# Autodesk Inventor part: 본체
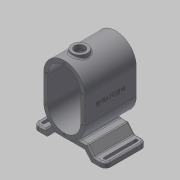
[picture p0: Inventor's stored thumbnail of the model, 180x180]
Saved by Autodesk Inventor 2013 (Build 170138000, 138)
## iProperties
Created: 2016-12
Part Number: 본체
Material: 알루미늄 6061
Document SubType Name: Modeling
Designer: mduedu
Density: 2.71 g/cm^3
Author: mduedu
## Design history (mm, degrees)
sketch "스케치1"
  geometry: L1 (40, -25)-(40, 25); L2 (-40, 25)-(-40, -25); L3 (-40, -25)-(40, 25); L4 (40, -25)-(-40, 25); L5 (0, 25)-(0, -25); A1 r 40 centre (0, 25) between (40, 25) and (-40, 25); A2 r 40 centre (0, -25) between (-40, -25) and (40, -25); 1 further point
  constraints: 10 end point, 4 point on circle, 3 tangent, 2 centre point, 2 midpoint, 2 parallel, 1 vertical
  dimensions: "d0" = 130 dimension on A2 A1; "d2" = 80 distance between parallel lines of L1 L2
extrude "돌출1" new body sketch "스케치1" stored distance "d3" = 100; taper "d4" = 0 deg
feature "쉘1" dims "d5" = 8
sketch "스케치15"
  geometry: L1 (-35, -64.5)-(35, -64.5); L2 (-35, -64.5)-(-47.586, -79.5); L3 (-47.586, -79.5)-(-70, -79.5); L4 (0, -64.5)-(0, 0); L5 (35, -64.5)-(47.586, -79.5); L6 (47.586, -79.5)-(70, -79.5); L7 (70, -89.5)-(42.923, -89.5); L8 (42.923, -89.5)-(30.337, -74.5); L9 (30.337, -74.5)-(-30.337, -74.5); L10 (-30.337, -74.5)-(-42.923, -89.5); L11 (-42.923, -89.5)-(-70, -89.5); L12 (-70, -79.5)-(-70, -89.5); L13 (70, -79.5)-(70, -89.5); A1 r 40 centre (0, -25) between (-40, -25) and (40, -25) reference; 1 further point
  constraints: 26 end point, 2 parallel, 2 perpendicular, 2 symmetric about line, 1 coincident, 1 horizontal, 1 midpoint, 1 vertical, 4 other
  dimensions: "d83" = 10 distance between parallel lines of L9 L1; "d85" = 140 distance between parallel lines of L13 L12; "d86" = 70 distance of L1.start L1.end; "d87" = 25 distance between parallel lines of L11 L1; "d88" = 130 deg angle of L1 L2; "d106" = 0.5 distance edge to line of A1 L1
extrude "돌출6" new body sketch "스케치15" stored distance "d89" = 80; taper "d90" = 0 deg
fillet "모깎기13" dims "d101" = 3
fillet "모깎기15" dims "d103" = 3
fillet "모깎기16" dims "d104" = 10
fillet "모깎기17" dims "d105" = 3
feature "결합2"
  node "솔리드2"
fillet "모깎기18" dims "d107" = 3
sketch "스케치16"
  geometry: L1 (8.015, 67)-(8.015, 7); L2 (14.015, 67)-(14.015, 7); A1 r 10 centre (11.015, 67) between (21.015, 67) and (11.015, 77) reference; A2 r 10 centre (11.015, 7) between (11.015, -3) and (21.015, 7) reference; A3 r 3 centre (11.015, 67) between (8.015, 67) and (14.015, 67); A4 r 3 centre (11.015, 7) between (8.015, 7) and (14.015, 7); 1 further point
  constraints: 4 end point, 4 point on circle, 4 tangent, 2 centre point, 2 coincident
  dimensions: "d108" = 6 diameter of A3; "d109" = 6 diameter of A4
extrude "돌출7" cut sketch "스케치16" stored distance "d110" = 80; taper "d111" = 0 deg
node "작업 평면1"
sketch "스케치9"
  geometry: 1 further point
sketch "스케치7"
  geometry: L1 (40, 50)-(-40, 50) reference; C1 r 15 at (0, 20); 1 further point
  constraints: 1 centre point, 1 vertical alignment
  dimensions: "d40" = 30 diameter of C1; "d41" = 30 distance from line of C1.centre L1
extrude "돌출4" join sketch "스케치7" stored distance "d42" = 80; taper "d43" = 0 deg
hole "구멍2" diameter "d46" = 20; stored, may be unused: countersink angle "d50" = 90 deg, drill point angle "d52" = 118 deg; dims "d44" = 10, "d45" = 10, "d47" = 6, "d48" = 4, "d49" = 2, "d51" = 8
fillet "모깎기4" dims "d53" = 3
node "작업 평면2"
sketch "스케치8"
  geometry: C1 r 15 at (0, 0) reference; C2 r 15 at (0, 0); 1 further point
  constraints: 1 centre point, 1 coincident
  dimensions: "d55" = 30 diameter of C2
extrude "돌출5" cut sketch "스케치8" stored distance "d56" = 80; taper "d57" = 0 deg
chamfer "모따기1" distance "d58" = 1; stored, may be unused: second distance "d59" = 2, angle "d60" = 45 deg
sketch "스케치10"
  geometry: 2 further points
  constraints: 1 coincident, 1 other
feature "엠보싱1" sketch "스케치10" dims "d0" = 130, "d2" = 80, "d61" = 0.5, "d62" = 0
sketch "스케치11"
  geometry: 1 further point
  constraints: 1 other
hole "구멍3" sketch "스케치11" at (0, 60) diameter "d63" = 3.242; stored, may be unused: countersink angle "d67" = 90 deg, drill point angle "d69" = 120 deg; dims "d64" = 8.6, "d65" = 4, "d66" = 2, "d68" = 10.6
sketch "스케치12"
  geometry: 1 further point
  constraints: 1 other
hole "구멍5" sketch "스케치12" at (0, 60) diameter "d70" = 3.242; stored, may be unused: countersink angle "d74" = 90 deg, drill point angle "d76" = 120 deg; dims "d71" = 8.6, "d72" = 4, "d73" = 2, "d75" = 10.6
node "솔리드1"
mirror "대칭2"
pattern_linear "직사각형 패턴1"
pattern_linear "직사각형 패턴2"
sketch "스케치13"
  geometry: L1 (-40, 25)-(-40, -25) reference; L2 (40, -25)-(40, 25) reference; L3 (35, 25)-(35, -25); L4 (-35, -25)-(-35, 25); A1 r 40 centre (0, 25) between (40, 25) and (-40, 25) reference; A2 r 40 centre (0, -25) between (-40, -25) and (40, -25) reference; A3 r 35 centre (0, 25) between (35, 25) and (-35, 25); A4 r 35 centre (0, -25) between (-35, -25) and (35, -25); 2 further points
  constraints: 5 point on circle, 4 end point, 2 centre point, 3 other
  dimensions: "d77" = 5 distance between parallel lines of L3 L2
sketch "스케치14"
  geometry: L1 (-40, 25)-(-40, -25) reference; L2 (40, -25)-(40, 25) reference; L3 (35, 25)-(35, -25); L4 (-35, -25)-(-35, 25); A1 r 40 centre (0, 25) between (40, 25) and (-40, 25) reference; A2 r 40 centre (0, -25) between (-40, -25) and (40, -25) reference; A3 r 35 centre (0, 25) between (35, 25) and (-35, 25); A4 r 35 centre (0, -25) between (-35, -25) and (35, -25); 2 further points
  constraints: 5 point on circle, 4 end point, 2 centre point, 3 other
  dimensions: "d80" = 5 distance between parallel lines of L2 L3
other parameters: "d54" = -8
